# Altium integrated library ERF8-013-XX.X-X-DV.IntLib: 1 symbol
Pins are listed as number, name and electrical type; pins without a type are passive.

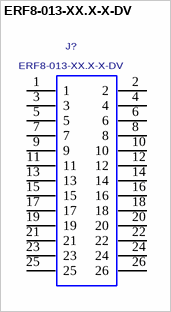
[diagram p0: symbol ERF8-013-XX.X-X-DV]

## ERF8-013-XX.X-X-DV
designator J?
0.8mm Socket Assembly, Double Vertical Row, 13 Positions Per Row.; MANUFACTURER: SAMTEC
footprint ERF8-013-XX.X-X-DV
pins: 1, 2, 3, 4, 5, 6, 7, 8, 9, 10, 11, 12, 13, 14, 15, 16, 17, 18, 19, 20, 21, 22, 23, 24, 25, 26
